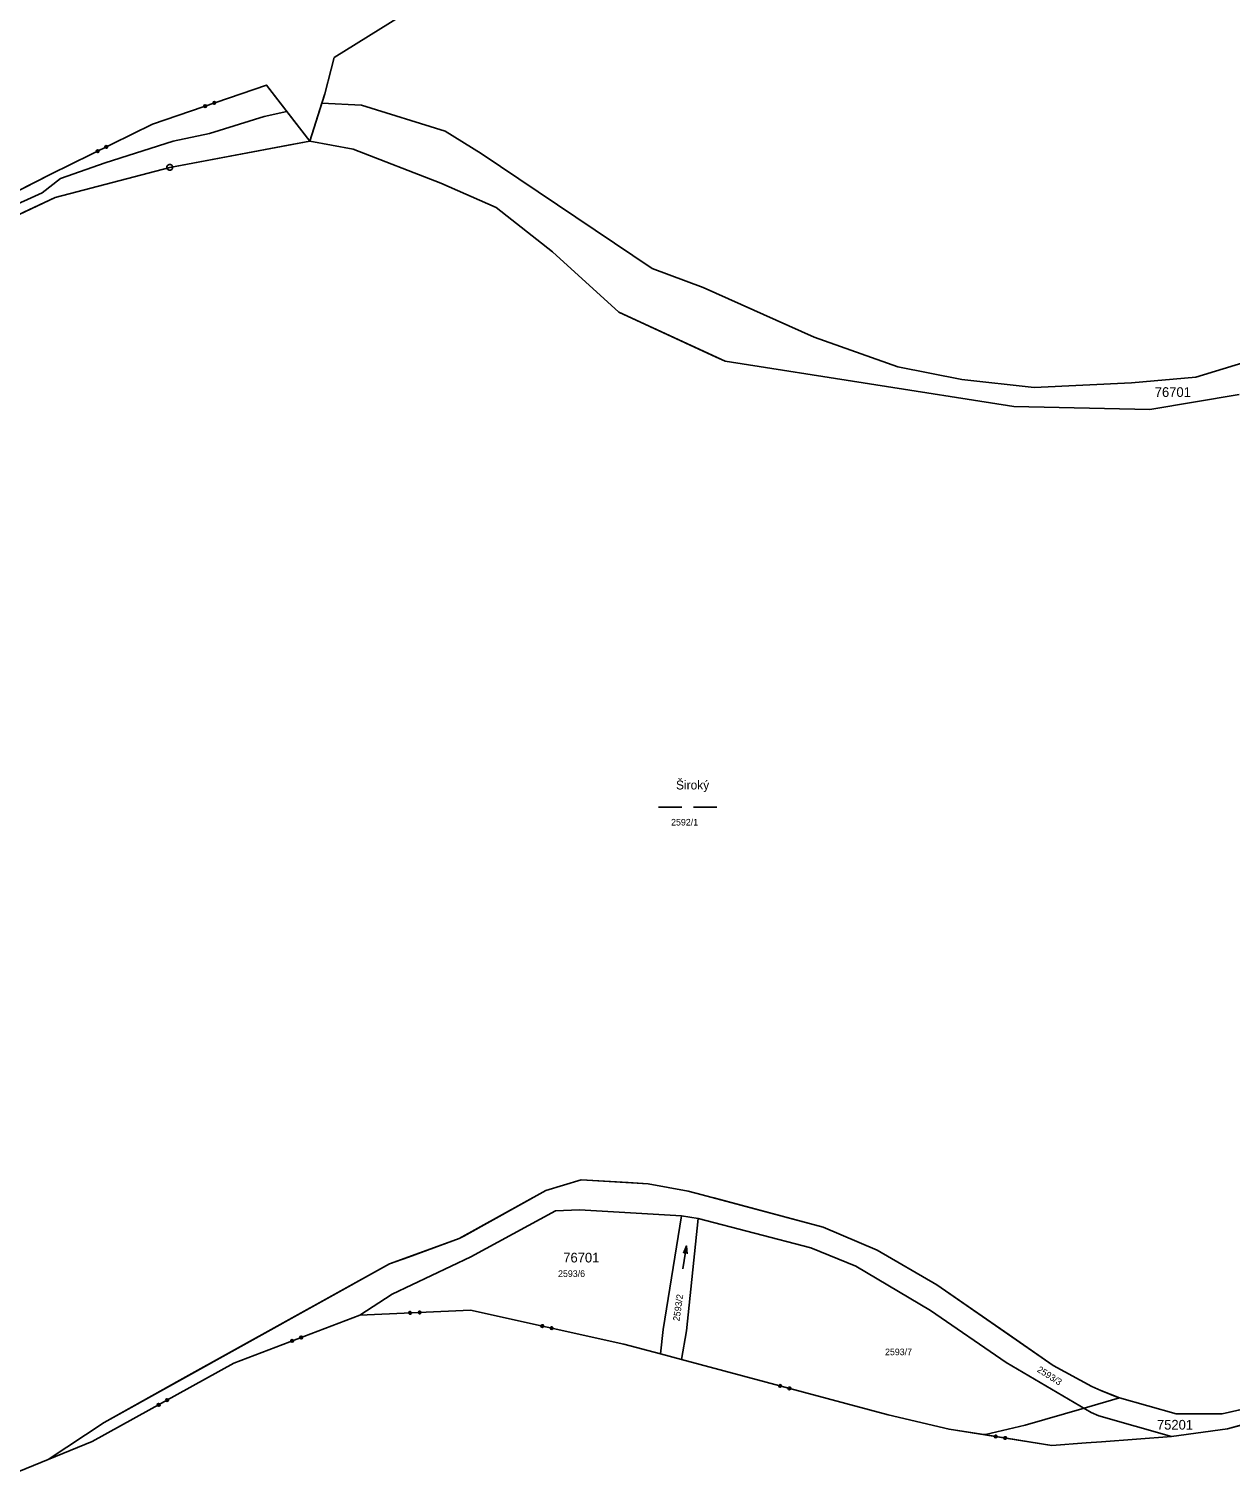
# Model space of a CAD drawing. Extents: x -760611 to -758411, y -1176479 to -1174807.
# Drawn here: x -760429.8 to -760120.3, y -1176472.8 to -1176098.4 of the extents above; entities that cross this region are included whole.
import ezdxf

# ---------------------------------------------------------------- set-up
doc = ezdxf.new("R2010")
doc.units = 0
for name, color, linetype in [('1', 7, 'Continuous'), ('11', 7, 'Continuous'), ('2', 7, 'Continuous'), ('3', 7, 'Continuous'), ('7', 7, 'Continuous'), ('8', 7, 'Continuous')]:
    doc.layers.add(name, color=color, linetype=linetype)

msp = doc.modelspace()

# ---------------------------------------------------------------- linework, layer by layer
at = {"layer": '1'}
for p, q in [((-760351.99, -1176108.74), (-760351.21, -1176105.78)), ((-760353.61, -1176115.11), (-760351.99, -1176108.74)), ((-760397.95, -1176122.89), (-760368.61, -1176112.84)), ((-760368.61, -1176112.84), (-760357.48, -1176127.31)), ((-760357.48, -1176127.31), (-760353.61, -1176115.11)), ((-760424.14, -1176135.79), (-760397.95, -1176122.89)), ((-760393.52, -1176134.03), (-760357.48, -1176127.31)), ((-760346.36, -1176129.35), (-760357.48, -1176127.31)), ((-760323.72, -1176138.12), (-760346.36, -1176129.35)), ((-760460.11, -1176154.07), (-760424.14, -1176135.79)), ((-760423.07, -1176141.77), (-760393.52, -1176134.03)), ((-760309.47, -1176144.4), (-760323.72, -1176138.12)), ((-760443.32, -1176151.33), (-760423.07, -1176141.77)), ((-760295.03, -1176155.81), (-760309.47, -1176144.4)), ((-760277.96, -1176171.31), (-760295.03, -1176155.81)), ((-760250.57, -1176183.98), (-760277.96, -1176171.31)), ((-760176.21, -1176195.59), (-760250.57, -1176183.98)), ((-760118.18, -1176192.52), (-760141.19, -1176196.35)), ((-760141.19, -1176196.35), (-760176.21, -1176195.59)), ((-760287.61, -1176394.76), (-760296.71, -1176397.49)), ((-760270.38, -1176395.79), (-760287.61, -1176394.76)), ((-760260.08, -1176397.69), (-760270.38, -1176395.79)), ((-760296.71, -1176397.49), (-760319.05, -1176409.9)), ((-760256.46, -1176398.58), (-760260.08, -1176397.69)), ((-760225.35, -1176406.98), (-760256.46, -1176398.58)), ((-760294.26, -1176402.73), (-760316.04, -1176414.6)), ((-760288.04, -1176402.49), (-760294.26, -1176402.73)), ((-760261.83, -1176404.03), (-760288.04, -1176402.49)), ((-760266.54, -1176433.25), (-760261.83, -1176404.03)), ((-760261.83, -1176404.03), (-760257.52, -1176404.7)), ((-760257.52, -1176404.7), (-760260.46, -1176433.63)), ((-760228.5, -1176412.29), (-760257.52, -1176404.7)), ((-760211.42, -1176412.86), (-760225.35, -1176406.98)), ((-760319.05, -1176409.9), (-760337, -1176416.4)), ((-760216.89, -1176417), (-760228.5, -1176412.29)), ((-760196.09, -1176421.76), (-760211.42, -1176412.86)), ((-760337, -1176416.4), (-760410.44, -1176457.23)), ((-760316.04, -1176414.6), (-760336.32, -1176424.2)), ((-760197.71, -1176428.4), (-760216.89, -1176417)), ((-760166.12, -1176442.52), (-760196.09, -1176421.76)), ((-760336.32, -1176424.2), (-760344.63, -1176429.59)), ((-760316.13, -1176428.34), (-760344.63, -1176429.59)), ((-760276.6, -1176437.03), (-760316.13, -1176428.34)), ((-760178.22, -1176441.78), (-760197.71, -1176428.4)), ((-760344.63, -1176429.59), (-760377.01, -1176441.98)), ((-760267.18, -1176439.56), (-760266.54, -1176433.25)), ((-760260.46, -1176433.63), (-760261.76, -1176441.01)), ((-760267.18, -1176439.56), (-760276.6, -1176437.03)), ((-760261.76, -1176441.01), (-760267.18, -1176439.56)), ((-760377.01, -1176441.98), (-760413.52, -1176462.15)), ((-760208.55, -1176455.27), (-760261.76, -1176441.01)), ((-760156.28, -1176454.63), (-760178.22, -1176441.78)), ((-760156.13, -1176447.98), (-760166.12, -1176442.52)), ((-760153.87, -1176448.99), (-760156.13, -1176447.98)), ((-760149.06, -1176450.91), (-760153.87, -1176448.99)), ((-760134.42, -1176455.01), (-760149.06, -1176450.91)), ((-760108.22, -1176451.75), (-760122.62, -1176455.05)), ((-760192.88, -1176458.96), (-760208.55, -1176455.27)), ((-760154.37, -1176455.53), (-760156.28, -1176454.63)), ((-760135.67, -1176460.84), (-760154.37, -1176455.53)), ((-760122.62, -1176455.05), (-760134.42, -1176455.01)), ((-760106.95, -1176454.96), (-760121.19, -1176458.87)), ((-760410.44, -1176457.23), (-760424.82, -1176466.77)), ((-760166.44, -1176463.13), (-760192.88, -1176458.96)), ((-760121.19, -1176458.87), (-760135.67, -1176460.84)), ((-760413.52, -1176462.15), (-760424.82, -1176466.77)), ((-760157.62, -1176462.47), (-760166.44, -1176463.13)), ((-760153.69, -1176462.18), (-760157.62, -1176462.47)), ((-760135.67, -1176460.84), (-760153.69, -1176462.18)), ((-760439.57, -1176472.8), (-760424.82, -1176466.77))]:
    msp.add_line(p, q, dxfattribs=at)
for points in [[(-760384.4, -1176117.91), (-760384.15, -1176118.03), (-760384.07, -1176118.28), (-760384.19, -1176118.52), (-760384.44, -1176118.61), (-760384.68, -1176118.49), (-760384.77, -1176118.24), (-760384.65, -1176118), (-760384.4, -1176117.91), (-760384.39, -1176117.95), (-760384.62, -1176118.03), (-760384.67, -1176118.13), (-760384.29, -1176118), (-760384.19, -1176118.05), (-760384.72, -1176118.23), (-760384.69, -1176118.31), (-760384.16, -1176118.13), (-760384.14, -1176118.2), (-760384.67, -1176118.38), (-760384.64, -1176118.46), (-760384.11, -1176118.28), (-760384.16, -1176118.38), (-760384.54, -1176118.51), (-760384.44, -1176118.56), (-760384.21, -1176118.48)], [(-760382.03, -1176117.1), (-760381.79, -1176117.22), (-760381.7, -1176117.47), (-760381.82, -1176117.71), (-760382.08, -1176117.8), (-760382.32, -1176117.68), (-760382.4, -1176117.43), (-760382.29, -1176117.19), (-760382.03, -1176117.1), (-760382.05, -1176117.15), (-760382.27, -1176117.22), (-760382.32, -1176117.33), (-760381.94, -1176117.2), (-760381.84, -1176117.25), (-760382.37, -1176117.43), (-760382.35, -1176117.5), (-760381.82, -1176117.32), (-760381.79, -1176117.4), (-760382.32, -1176117.58), (-760382.3, -1176117.65), (-760381.77, -1176117.47), (-760381.82, -1176117.57), (-760382.19, -1176117.7), (-760382.09, -1176117.75), (-760381.86, -1176117.68)], [(-760412.15, -1176129.53), (-760411.89, -1176129.61), (-760411.77, -1176129.85), (-760411.86, -1176130.11), (-760412.1, -1176130.23), (-760412.36, -1176130.14), (-760412.47, -1176129.9), (-760412.39, -1176129.65), (-760412.15, -1176129.53), (-760412.14, -1176129.57), (-760412.35, -1176129.67), (-760412.39, -1176129.78), (-760412.03, -1176129.6), (-760411.92, -1176129.64), (-760412.43, -1176129.89), (-760412.39, -1176129.96), (-760411.89, -1176129.71), (-760411.85, -1176129.78), (-760412.35, -1176130.03), (-760412.32, -1176130.1), (-760411.82, -1176129.85), (-760411.85, -1176129.96), (-760412.21, -1176130.14), (-760412.11, -1176130.17), (-760411.89, -1176130.07)], [(-760409.9, -1176128.42), (-760409.65, -1176128.51), (-760409.53, -1176128.75), (-760409.62, -1176129), (-760409.86, -1176129.12), (-760410.11, -1176129.04), (-760410.23, -1176128.79), (-760410.15, -1176128.54), (-760409.9, -1176128.42), (-760409.91, -1176128.47), (-760410.13, -1176128.58), (-760410.16, -1176128.68), (-760409.81, -1176128.51), (-760409.7, -1176128.54), (-760410.2, -1176128.79), (-760410.17, -1176128.86), (-760409.66, -1176128.61), (-760409.63, -1176128.69), (-760410.13, -1176128.93), (-760410.1, -1176129.01), (-760409.59, -1176128.76), (-760409.63, -1176128.86), (-760409.99, -1176129.04), (-760409.88, -1176129.08), (-760409.67, -1176128.97)], [(-760331.79, -1176429.35), (-760331.99, -1176429.17), (-760332, -1176428.9), (-760331.82, -1176428.7), (-760331.55, -1176428.69), (-760331.36, -1176428.87), (-760331.34, -1176429.14), (-760331.53, -1176429.34), (-760331.79, -1176429.35), (-760331.77, -1176429.31), (-760331.53, -1176429.3), (-760331.45, -1176429.21), (-760331.85, -1176429.23), (-760331.93, -1176429.15), (-760331.37, -1176429.13), (-760331.38, -1176429.05), (-760331.94, -1176429.07), (-760331.94, -1176428.99), (-760331.38, -1176428.97), (-760331.38, -1176428.89), (-760331.94, -1176428.91), (-760331.87, -1176428.83), (-760331.47, -1176428.81), (-760331.55, -1176428.74), (-760331.79, -1176428.75)], [(-760329.3, -1176429.24), (-760329.5, -1176429.06), (-760329.51, -1176428.79), (-760329.33, -1176428.59), (-760329.06, -1176428.58), (-760328.86, -1176428.76), (-760328.85, -1176429.03), (-760329.03, -1176429.23), (-760329.3, -1176429.24), (-760329.29, -1176429.2), (-760329.05, -1176429.19), (-760328.97, -1176429.1), (-760329.37, -1176429.12), (-760329.46, -1176429.04), (-760328.9, -1176429.02), (-760328.9, -1176428.94), (-760329.46, -1176428.97), (-760329.46, -1176428.89), (-760328.9, -1176428.86), (-760328.91, -1176428.78), (-760329.47, -1176428.81), (-760329.39, -1176428.72), (-760328.99, -1176428.7), (-760329.07, -1176428.63), (-760329.31, -1176428.64)], [(-760297.83, -1176432.69), (-760297.98, -1176432.46), (-760297.92, -1176432.2), (-760297.69, -1176432.06), (-760297.43, -1176432.11), (-760297.28, -1176432.34), (-760297.34, -1176432.6), (-760297.57, -1176432.75), (-760297.83, -1176432.69), (-760297.79, -1176432.66), (-760297.56, -1176432.71), (-760297.46, -1176432.65), (-760297.85, -1176432.56), (-760297.91, -1176432.47), (-760297.37, -1176432.59), (-760297.35, -1176432.51), (-760297.9, -1176432.39), (-760297.88, -1176432.31), (-760297.33, -1176432.43), (-760297.32, -1176432.35), (-760297.86, -1176432.23), (-760297.77, -1176432.17), (-760297.38, -1176432.26), (-760297.44, -1176432.16), (-760297.67, -1176432.11)], [(-760295.39, -1176433.23), (-760295.53, -1176433), (-760295.48, -1176432.74), (-760295.25, -1176432.59), (-760294.99, -1176432.65), (-760294.84, -1176432.88), (-760294.9, -1176433.14), (-760295.13, -1176433.29), (-760295.39, -1176433.23), (-760295.37, -1176433.19), (-760295.14, -1176433.24), (-760295.04, -1176433.18), (-760295.43, -1176433.1), (-760295.49, -1176433), (-760294.95, -1176433.12), (-760294.93, -1176433.04), (-760295.48, -1176432.92), (-760295.46, -1176432.84), (-760294.91, -1176432.96), (-760294.89, -1176432.89), (-760295.44, -1176432.77), (-760295.35, -1176432.7), (-760294.95, -1176432.79), (-760295.02, -1176432.7), (-760295.25, -1176432.64)], [(-760362.04, -1176436.59), (-760362.29, -1176436.49), (-760362.38, -1176436.23), (-760362.27, -1176435.99), (-760362.02, -1176435.89), (-760361.78, -1176436), (-760361.68, -1176436.25), (-760361.79, -1176436.5), (-760362.04, -1176436.59), (-760362.03, -1176436.55), (-760361.8, -1176436.46), (-760361.76, -1176436.36), (-760362.13, -1176436.5), (-760362.23, -1176436.45), (-760361.71, -1176436.25), (-760361.74, -1176436.18), (-760362.26, -1176436.38), (-760362.29, -1176436.31), (-760361.77, -1176436.1), (-760361.8, -1176436.03), (-760362.32, -1176436.23), (-760362.27, -1176436.13), (-760361.9, -1176435.98), (-760362, -1176435.94), (-760362.23, -1176436.02)], [(-760359.71, -1176435.7), (-760359.95, -1176435.59), (-760360.05, -1176435.34), (-760359.94, -1176435.09), (-760359.69, -1176435), (-760359.44, -1176435.11), (-760359.34, -1176435.36), (-760359.45, -1176435.61), (-760359.71, -1176435.7), (-760359.71, -1176435.66), (-760359.49, -1176435.57), (-760359.44, -1176435.47), (-760359.81, -1176435.61), (-760359.92, -1176435.57), (-760359.39, -1176435.37), (-760359.42, -1176435.29), (-760359.95, -1176435.49), (-760359.98, -1176435.42), (-760359.45, -1176435.22), (-760359.48, -1176435.14), (-760360, -1176435.34), (-760359.96, -1176435.24), (-760359.58, -1176435.1), (-760359.69, -1176435.05), (-760359.91, -1176435.14)], [(-760236.62, -1176448.08), (-760236.75, -1176447.85), (-760236.68, -1176447.59), (-760236.45, -1176447.45), (-760236.19, -1176447.52), (-760236.06, -1176447.75), (-760236.13, -1176448.01), (-760236.36, -1176448.15), (-760236.62, -1176448.08), (-760236.58, -1176448.05), (-760236.35, -1176448.11), (-760236.25, -1176448.05), (-760236.64, -1176447.95), (-760236.69, -1176447.85), (-760236.15, -1176448), (-760236.13, -1176447.92), (-760236.67, -1176447.78), (-760236.65, -1176447.7), (-760236.11, -1176447.84), (-760236.09, -1176447.77), (-760236.63, -1176447.62), (-760236.53, -1176447.56), (-760236.15, -1176447.67), (-760236.2, -1176447.57), (-760236.43, -1176447.51)], [(-760234.2, -1176448.73), (-760234.34, -1176448.49), (-760234.27, -1176448.23), (-760234.04, -1176448.1), (-760233.78, -1176448.17), (-760233.64, -1176448.4), (-760233.71, -1176448.66), (-760233.94, -1176448.8), (-760234.2, -1176448.73), (-760234.18, -1176448.69), (-760233.95, -1176448.75), (-760233.85, -1176448.7), (-760234.24, -1176448.59), (-760234.3, -1176448.49), (-760233.76, -1176448.64), (-760233.74, -1176448.56), (-760234.28, -1176448.42), (-760234.26, -1176448.34), (-760233.72, -1176448.48), (-760233.69, -1176448.41), (-760234.24, -1176448.26), (-760234.14, -1176448.21), (-760233.75, -1176448.31), (-760233.81, -1176448.21), (-760234.04, -1176448.15)], [(-760394.17, -1176451.83), (-760394.43, -1176451.75), (-760394.56, -1176451.52), (-760394.49, -1176451.26), (-760394.25, -1176451.13), (-760393.99, -1176451.2), (-760393.86, -1176451.44), (-760393.94, -1176451.7), (-760394.17, -1176451.83), (-760394.18, -1176451.79), (-760393.97, -1176451.67), (-760393.94, -1176451.56), (-760394.29, -1176451.76), (-760394.4, -1176451.73), (-760393.91, -1176451.45), (-760393.95, -1176451.38), (-760394.44, -1176451.66), (-760394.48, -1176451.59), (-760393.99, -1176451.31), (-760394.03, -1176451.24), (-760394.52, -1176451.52), (-760394.49, -1176451.41), (-760394.14, -1176451.21), (-760394.24, -1176451.18), (-760394.45, -1176451.3)], [(-760396.36, -1176453.04), (-760396.62, -1176452.96), (-760396.75, -1176452.73), (-760396.68, -1176452.47), (-760396.44, -1176452.34), (-760396.18, -1176452.41), (-760396.05, -1176452.65), (-760396.13, -1176452.91), (-760396.36, -1176453.04), (-760396.36, -1176452.99), (-760396.15, -1176452.87), (-760396.11, -1176452.76), (-760396.46, -1176452.96), (-760396.57, -1176452.92), (-760396.08, -1176452.65), (-760396.12, -1176452.58), (-760396.61, -1176452.85), (-760396.65, -1176452.78), (-760396.16, -1176452.51), (-760396.2, -1176452.44), (-760396.69, -1176452.71), (-760396.66, -1176452.61), (-760396.31, -1176452.41), (-760396.42, -1176452.38), (-760396.63, -1176452.5)], [(-760181.12, -1176461.14), (-760181.28, -1176460.92), (-760181.24, -1176460.65), (-760181.02, -1176460.5), (-760180.75, -1176460.54), (-760180.6, -1176460.76), (-760180.64, -1176461.02), (-760180.86, -1176461.18), (-760181.12, -1176461.14), (-760181.09, -1176461.1), (-760180.85, -1176461.14), (-760180.76, -1176461.07), (-760181.15, -1176461.01), (-760181.22, -1176460.92), (-760180.67, -1176461.01), (-760180.65, -1176460.93), (-760181.21, -1176460.84), (-760181.19, -1176460.76), (-760180.64, -1176460.85), (-760180.63, -1176460.77), (-760181.18, -1176460.68), (-760181.09, -1176460.62), (-760180.7, -1176460.68), (-760180.76, -1176460.59), (-760181, -1176460.55)], [(-760178.65, -1176461.53), (-760178.81, -1176461.31), (-760178.77, -1176461.04), (-760178.55, -1176460.89), (-760178.28, -1176460.93), (-760178.13, -1176461.15), (-760178.17, -1176461.41), (-760178.39, -1176461.57), (-760178.65, -1176461.53), (-760178.64, -1176461.49), (-760178.4, -1176461.53), (-760178.31, -1176461.46), (-760178.7, -1176461.4), (-760178.77, -1176461.31), (-760178.22, -1176461.39), (-760178.2, -1176461.32), (-760178.76, -1176461.23), (-760178.75, -1176461.15), (-760178.19, -1176461.24), (-760178.18, -1176461.16), (-760178.73, -1176461.07), (-760178.64, -1176461), (-760178.25, -1176461.07), (-760178.31, -1176460.97), (-760178.55, -1176460.94)]]:
    msp.add_lwpolyline(points, dxfattribs=at)
at = {"layer": '11'}
for p, q in [((-760357.48, -1176127.31), (-760354.36, -1176117.47)), ((-760363.38, -1176119.64), (-760357.48, -1176127.31))]:
    msp.add_line(p, q, dxfattribs=at)
for points in [[(-760354.36, -1176117.47), (-760353.61, -1176115.11), (-760351.99, -1176108.74), (-760351.21, -1176105.78), (-760322.24, -1176087.67), (-760311.29, -1176078.48), (-760305.7, -1176066.58), (-760304.23, -1176054.57), (-760307.13, -1175963.75), (-760299.16, -1175941.42), (-760278.28, -1175902.33), (-760268.38, -1175877.22), (-760243.64, -1175828.02), (-760242.05, -1175824.48), (-760234.44, -1175807.53), (-760232.38, -1175802.95)], [(-760610.45, -1176430.21), (-760609.56, -1176423.39), (-760585.17, -1176405.4), (-760559.85, -1176375.71), (-760537.67, -1176346.05), (-760532.8, -1176335.28), (-760530.31, -1176321.04), (-760535.16, -1176185.8), (-760460.11, -1176154.07), (-760424.14, -1176135.79), (-760397.95, -1176122.89), (-760368.61, -1176112.84), (-760363.38, -1176119.64)], [(-759995.2, -1176195.3), (-760000, -1176195.1), (-760003.44, -1176195.11), (-760050.76, -1176182.79), (-760064.91, -1176179.67), (-760069.67, -1176178.62), (-760080.79, -1176177.14), (-760084.65, -1176177.25), (-760090.13, -1176177.39), (-760102.05, -1176179.71), (-760129.34, -1176188.09), (-760145.91, -1176189.48), (-760170.97, -1176190.7), (-760189.6, -1176188.66), (-760206.1, -1176185.39), (-760227.61, -1176177.78), (-760256.25, -1176164.96), (-760269.32, -1176160.06), (-760313.39, -1176130.43), (-760322.62, -1176124.75), (-760344.15, -1176117.99), (-760354.36, -1176117.47)], [(-760363.38, -1176119.64), (-760369.24, -1176120.91), (-760383.31, -1176125.31), (-760392.68, -1176127.25), (-760410.17, -1176132.85), (-760421.69, -1176136.87), (-760426.42, -1176140.6), (-760453.35, -1176152.8)], [(-760555.89, -1176460.89), (-760566.55, -1176433.11), (-760571.54, -1176420.09), (-760571.27, -1176415.93), (-760570.49, -1176404.12), (-760569.34, -1176401.64), (-760544.14, -1176367.23), (-760496.02, -1176307.61), (-760486.07, -1176264.19), (-760486.4, -1176243.86), (-760483.8, -1176236.76), (-760478.12, -1176221.24), (-760468.8, -1176193.32), (-760462.1, -1176173.26), (-760460.38, -1176169.87), (-760443.32, -1176151.33), (-760423.07, -1176141.77), (-760393.52, -1176134.03), (-760363.05, -1176128.35), (-760357.48, -1176127.31)], [(-760357.48, -1176127.31), (-760346.36, -1176129.35), (-760323.72, -1176138.12), (-760309.47, -1176144.4), (-760295.03, -1176155.81), (-760277.96, -1176171.31), (-760252.89, -1176182.9), (-760250.57, -1176183.98), (-760176.21, -1176195.59), (-760141.19, -1176196.35), (-760118.18, -1176192.52)], [(-760196.09, -1176421.76), (-760211.42, -1176412.86), (-760225.35, -1176406.98), (-760253.45, -1176399.39), (-760256.46, -1176398.58), (-760260.08, -1176397.69), (-760270.38, -1176395.79), (-760275.54, -1176395.48), (-760287.61, -1176394.76), (-760296.71, -1176397.49), (-760317.84, -1176409.23), (-760319.05, -1176409.9), (-760332.08, -1176414.64), (-760337, -1176416.4), (-760390.91, -1176446.3), (-760410.43, -1176457.23), (-760410.44, -1176457.23), (-760424.85, -1176466.78)], [(-760149.06, -1176450.91), (-760149.6, -1176450.7), (-760153.87, -1176448.99), (-760156.13, -1176447.98), (-760166.12, -1176442.52), (-760177.47, -1176434.66), (-760196.09, -1176421.76)], [(-760183.97, -1176460.36), (-760192.88, -1176458.96), (-760208.55, -1176455.27), (-760261.76, -1176441.01), (-760267.18, -1176439.56), (-760276.6, -1176437.03), (-760316.13, -1176428.34), (-760344.63, -1176429.59), (-760377.01, -1176441.98), (-760413.52, -1176462.15), (-760424.82, -1176466.77), (-760424.85, -1176466.78)], [(-760084.16, -1176443.66), (-760088.93, -1176445.26), (-760108.22, -1176451.75), (-760122.62, -1176455.05), (-760134.42, -1176455.01), (-760149.06, -1176450.91)], [(-760183.97, -1176460.36), (-760183.49, -1176460.3), (-760173.27, -1176457.95), (-760158.13, -1176453.55), (-760149.06, -1176450.91)], [(-760106.95, -1176454.96), (-760121.19, -1176458.87), (-760135.67, -1176460.84), (-760153.69, -1176462.18), (-760157.62, -1176462.47), (-760166.44, -1176463.13), (-760183.97, -1176460.36)]]:
    msp.add_lwpolyline(points, dxfattribs=at)
at = {"layer": '3'}
for p, q in [((-760267.68, -1176298.78), (-760261.68, -1176298.78)), ((-760258.68, -1176298.78), (-760252.68, -1176298.78)), ((-760261.47, -1176417.7), (-760260.49, -1176411.78))]:
    msp.add_line(p, q, dxfattribs=at)
msp.add_lwpolyline([(-760261.31, -1176413.67), (-760260.49, -1176411.78), (-760260.32, -1176413.84)], dxfattribs=at)
at = {"layer": '8'}
msp.add_line((-760393.57, -1176134.03), (-760393.47, -1176134.03), dxfattribs=at)
msp.add_lwpolyline([(-760393.33, -1176133.31), (-760392.99, -1176133.5), (-760392.8, -1176133.84), (-760392.8, -1176134.23), (-760392.99, -1176134.57), (-760393.33, -1176134.76), (-760393.72, -1176134.76), (-760394.06, -1176134.57), (-760394.25, -1176134.23), (-760394.25, -1176133.84), (-760394.06, -1176133.5), (-760393.72, -1176133.31)], close=True, dxfattribs=at)

# ---------------------------------------------------------------- texts
at = {"layer": '11'}
for s, p in [('76701', (-760139.94, -1176193.15)), ('76701', (-760292.23, -1176416.03)), ('75201', (-760139.38, -1176459.07))]:
    msp.add_text(s, height=2.5, dxfattribs=at).set_placement(p)
at = {"layer": '2'}
for s, p in [('2592/1', (-760264.47, -1176303.51)), ('2593/6', (-760293.57, -1176419.76)), ('2593/7', (-760209.39, -1176439.91))]:
    msp.add_text(s, height=1.7, dxfattribs=at).set_placement(p)
for s, rotation, p in [('2593/2', 81.7611, (-760262.32, -1176431.23)), ('2593/3', 327.56, (-760170.41, -1176444.04))]:
    msp.add_text(s, height=1.7, rotation=rotation, dxfattribs=at).set_placement(p)
at = {"layer": '7'}
msp.add_text('Široký', height=2.3, dxfattribs=at).set_placement((-760263.2, -1176294.23))

doc.saveas('drawing.dxf')
